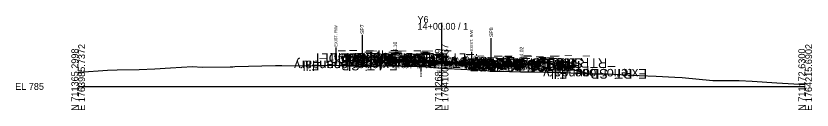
# Model space of a CAD drawing. Extents: x -26 to 1764234, y -10 to 711417.
# Drawn here: x -25.7 to 302.8, y 3990.3 to 4029 of the extents above; entities that cross this region are included whole.
import ezdxf

# ---------------------------------------------------------------- set-up
doc = ezdxf.new("R2010")
doc.units = 0
for name, color, linetype in [('Default', 7, 'Continuous'), ('Exist Cross Section Cell', 7, 'Continuous'), ('Exist XS Center Line Elevation Label', 7, 'Continuous'), ('Exist XS Ground Line', 7, 'Continuous'), ('Old_Level_10', 7, 'Continuous'), ('Prop CMT Conc Surface', 7, 'Continuous'), ('Prop CMT Concrete Structures', 7, 'Continuous'), ('Prop CMT Pvmt Course 1', 7, 'Continuous'), ('Prop CMT Pvmt Course 1 CG', 7, 'Continuous'), ('Prop CMT Pvmt Course 2', 7, 'Continuous'), ('Prop CMT Pvmt Course 3', 7, 'Continuous'), ('Prop CMT Pvmt Surface', 7, 'Continuous'), ('Prop CMT Slope Grass', 7, 'Continuous'), ('Prop CMT Subgrade Earthwork', 7, 'Continuous'), ('Prop XS Earthwork Shape', 7, 'Continuous'), ('Prop XS Hydro Elevations', 7, 'Continuous'), ('Prop XS SE Text', 7, 'Continuous'), ('Prop XS Shear Point Element', 7, 'Continuous'), ('Prop XS Shear Point Label', 7, 'Continuous'), ('Prop XS Side Slope Text', 7, 'Continuous'), ('Scratch_Level_7', 7, 'Continuous')]:
    doc.layers.add(name, color=color, linetype=linetype)

msp = doc.modelspace()

# ---------------------------------------------------------------- linework, layer by layer
at = {"layer": 'Exist Cross Section Cell'}
for p, q in [((150, 4000), (150, 4026.15)), ((0, 4000), (150, 4000)), ((150, 4000), (300, 4000))]:
    msp.add_line(p, q, dxfattribs=at)
at = {"layer": 'Exist XS Ground Line'}
msp.add_lwpolyline([(0, 4005.86), (0.45, 4005.87), (12.06, 4006.66), (16.03, 4006.86), (25.11, 4006.99), (31.6, 4007.29), (38.16, 4007.69), (47.17, 4008.15), (51.21, 4007.99), (62.74, 4008.02), (63.8, 4008.12), (64.63, 4008.19), (81.43, 4008.58), (84, 4008.56), (94.28, 4008.5), (95.25, 4008.52), (95.84, 4008.53), (98.52, 4008.59), (99.73, 4008.62), (101.78, 4008.65), (103.62, 4008.7), (105.04, 4008.72), (107.52, 4008.64), (108.3, 4008.61), (111.56, 4008.47), (112.35, 4008.45), (115.04, 4008.38), (117.48, 4008.34), (118.51, 4008.29), (119.6, 4008.35), (120.21, 4008.44), (120.97, 4008.37), (121.35, 4008.36), (123.09, 4008.39), (124.61, 4008.42), (126.98, 4008.48), (127.87, 4008.49), (129.19, 4008.51), (129.93, 4008.52), (130.64, 4008.51), (131.28, 4008.49), (132.79, 4008.46), (134.39, 4008.4), (134.76, 4008.39), (137.65, 4008.34), (138.66, 4008.32), (139.89, 4008.3), (140.8, 4008.27), (141.45, 4008.24), (143.36, 4008.06), (150, 4007.53), (151.69, 4007.4), (152.53, 4007.34), (168.68, 4006.5), (169.94, 4006.35), (170.66, 4006.32), (173.38, 4006.32), (182.5, 4006.05), (188.46, 4006.02), (193.38, 4005.87), (194.39, 4005.86), (201.11, 4005.81), (210.23, 4005.22), (218.47, 4005.21), (220.83, 4005.07), (226.85, 4004.79), (231.52, 4004.49), (238.57, 4004.21), (246.23, 4003.88), (249.17, 4003.68), (261.86, 4002.42), (272.69, 4002.41), (278.12, 4002.22), (288.3, 4001.56), (295.35, 4001.03), (300, 4000.74)], dxfattribs=at)
at = {"layer": 'Old_Level_10'}
for p, q in [((106.29, 4016.08), (106.29, 4008.68)), ((162.3, 4014.23), (162.3, 4006.83)), ((141.45, 4008.24), (141.45, 4006.19))]:
    msp.add_line(p, q, dxfattribs=at)
at = {"layer": 'Prop CMT Conc Surface'}
for points in [[(130.8, 4011.1), (130.8, 4011.6), (130.3, 4011.6)], [(132.8, 4011.1), (130.8, 4011.1)], [(180.97, 4009.18), (182.97, 4009.02)], [(182.97, 4009.02), (182.97, 4009.52), (183.47, 4009.52)]]:
    msp.add_lwpolyline(points, dxfattribs=at)
at = {"layer": 'Prop CMT Concrete Structures'}
for points in [[(132.8, 4011.1), (130.8, 4011.1), (130.8, 4011.6), (130.3, 4011.6)], [(130.3, 4011.6), (130.3, 4010.62), (132.8, 4010.52)], [(132.8, 4010.52), (132.8, 4011.1)], [(180.97, 4009.18), (182.97, 4009.02), (182.97, 4009.52), (183.47, 4009.52)], [(183.47, 4009.52), (183.47, 4008.49), (180.97, 4008.59)], [(180.97, 4008.59), (180.97, 4009.18)]]:
    msp.add_lwpolyline(points, dxfattribs=at)
at = {"layer": 'Prop CMT Pvmt Course 1'}
for points in [[(150, 4010.41), (132.8, 4011.1)], [(132.8, 4011.1), (132.8, 4010.85)], [(132.8, 4010.85), (150, 4010.16)], [(150, 4010.16), (150, 4010.41)], [(150, 4010.41), (180.97, 4009.18)], [(180.97, 4008.93), (150, 4010.16)], [(150, 4010.16), (150, 4010.16), (150, 4010.16), (150, 4010.16), (150, 4010.16)], [(180.97, 4009.18), (180.97, 4008.93)]]:
    msp.add_lwpolyline(points, dxfattribs=at)
msp.add_lwpolyline([(150, 4010.16), (150, 4010.16), (150, 4010.16), (150, 4010.16)], close=True, dxfattribs=at)
at = {"layer": 'Prop CMT Pvmt Course 1 CG'}
for points in [[(132.8, 4010.52), (129.8, 4010.64), (129.48, 4010.32)], [(129.48, 4010.32), (132.8, 4010.19)], [(132.8, 4010.19), (132.8, 4010.52)], [(180.97, 4008.59), (183.97, 4008.47), (184.32, 4008.12)], [(180.97, 4008.26), (180.97, 4008.59)], [(184.32, 4008.12), (180.97, 4008.26)]]:
    msp.add_lwpolyline(points, dxfattribs=at)
at = {"layer": 'Prop CMT Pvmt Course 2'}
for points in [[(150, 4010.16), (132.8, 4010.85)], [(132.8, 4010.85), (132.8, 4010.52)], [(132.8, 4010.52), (150, 4009.83)], [(150, 4009.83), (150, 4010.16)], [(150, 4009.83), (150, 4010.16)], [(150, 4010.16), (180.97, 4008.93)], [(180.97, 4008.59), (150, 4009.83)], [(180.97, 4008.93), (180.97, 4008.59)]]:
    msp.add_lwpolyline(points, dxfattribs=at)
at = {"layer": 'Prop CMT Pvmt Course 3'}
for points in [[(150, 4009.83), (132.8, 4010.52)], [(132.8, 4010.52), (132.8, 4010.19)], [(132.8, 4010.19), (150, 4009.5)], [(150, 4009.5), (150, 4009.83)], [(150, 4009.83), (180.97, 4008.59)], [(150, 4009.5), (150, 4009.83)], [(180.97, 4008.26), (150, 4009.5)], [(180.97, 4008.59), (180.97, 4008.26)]]:
    msp.add_lwpolyline(points, dxfattribs=at)
at = {"layer": 'Prop CMT Pvmt Surface'}
for points in [[(150, 4010.41), (132.8, 4011.1)], [(150, 4010.41), (180.97, 4009.18)]]:
    msp.add_lwpolyline(points, dxfattribs=at)
at = {"layer": 'Prop CMT Slope Grass'}
msp.add_line((117.37, 4011.3), (117.37, 4008.35), dxfattribs=at)
for points in [[(130.3, 4011.6), (120.8, 4011.79), (117.37, 4011.3)], [(183.47, 4009.52), (192.97, 4009.71), (210.92, 4005.22)]]:
    msp.add_lwpolyline(points, dxfattribs=at)
at = {"layer": 'Prop CMT Subgrade Earthwork'}
for points in [[(132.8, 4010.19), (129.48, 4010.32), (128.15, 4011.65)], [(150, 4009.5), (132.8, 4010.19)], [(150, 4009.5), (180.97, 4008.26)], [(180.97, 4008.26), (184.32, 4008.12), (185.75, 4009.56)]]:
    msp.add_lwpolyline(points, dxfattribs=at)
at = {"layer": 'Prop XS Earthwork Shape'}
msp.add_lwpolyline([(108.3, 4008.61), (111.56, 4008.47), (112.35, 4008.45), (115.04, 4008.38), (117.48, 4008.34), (118.51, 4008.29), (119.6, 4008.35), (120.21, 4008.44), (120.97, 4008.37), (121.35, 4008.36), (123.09, 4008.39), (124.61, 4008.42), (126.98, 4008.48), (127.87, 4008.49), (129.19, 4008.51), (129.93, 4008.52), (130.64, 4008.51), (131.28, 4008.49), (132.79, 4008.46), (134.39, 4008.4), (134.76, 4008.39), (137.65, 4008.34), (138.66, 4008.32), (139.89, 4008.3), (140.8, 4008.27), (141.45, 4008.24), (143.36, 4008.06), (150, 4007.53), (151.69, 4007.4), (152.53, 4007.34), (168.68, 4006.5), (169.94, 4006.35), (170.66, 4006.32), (173.38, 4006.32), (182.5, 4006.05), (188.46, 4006.02), (193.38, 4005.87), (194.39, 4005.86), (201.11, 4005.81), (210.23, 4005.22), (210.92, 4005.22), (192.97, 4009.71), (185.75, 4009.56), (184.32, 4008.12), (180.97, 4008.26), (150, 4009.5), (132.8, 4010.19), (129.48, 4010.32), (128.15, 4011.65), (120.8, 4011.79), (108.11, 4008.62)], close=True, dxfattribs=at)
at = {"layer": 'Prop XS Shear Point Element'}
for p, q in [((117.37, 4011.3), (117.37, 4021.23)), ((170.43, 4009.6), (170.43, 4019.88))]:
    msp.add_line(p, q, dxfattribs=at)

# ---------------------------------------------------------------- texts
at = {"layer": 'Default'}
msp.add_text('-', height=0.0001, dxfattribs=at).set_placement((0, 4000))
at = {"layer": 'Exist Cross Section Cell'}
for s, p in [('Y6', (140, 4026.15)), ('14+00.00 / 1', (140, 4023.35)), ('EL 785', (-26, 3998.6))]:
    msp.add_text(s, height=2.8, dxfattribs=at).set_placement(p)
for s, p in [('N 711365.2998', (0, 3990)), ('E 1763985.7372', (2.8, 3990)), ('N 711268.9649', (150, 3990)), ('E 1764100.7137', (152.8, 3990)), ('N 711172.6300', (300, 3990)), ('E 1764215.6902', (302.8, 3990))]:
    msp.add_text(s, height=2.8, rotation=90, dxfattribs=at).set_placement(p)
at = {"layer": 'Exist XS Center Line Elevation Label'}
msp.add_text('792.53', height=1, dxfattribs=at).set_placement((147.88, 4005.53))
at = {"layer": 'Old_Level_10'}
for s, height, p in [('EXIST. R/W', 1.181, (106.88, 4016.38)), ('EXIST. R/W', 1.181, (162.89, 4014.54)), ('EOP', 0.787, (141.85, 4003.79))]:
    msp.add_text(s, height=height, rotation=90, dxfattribs=at).set_placement(p)
at = {"layer": 'Prop XS Hydro Elevations'}
for s, p in [('796.10', (131.55, 4012.1)), ('794.02', (183.72, 4010.02))]:
    msp.add_text(s, height=1.5, rotation=90, dxfattribs=at).set_placement(p)
at = {"layer": 'Prop XS SE Text'}
for p in [(138.82, 4011.86), (162.9, 4010.9)]:
    msp.add_text('0.040', height=1.5, rotation=357.7094, dxfattribs=at).set_placement(p)
at = {"layer": 'Prop XS Shear Point Label'}
for s, p in [('SP7', (117.99, 4021.59)), ('SP8', (171.18, 4020.36))]:
    msp.add_text(s, height=1.5, rotation=90, dxfattribs=at).set_placement(p)
at = {"layer": 'Prop XS Side Slope Text'}
for s, rotation, p in [('VAR.', 14.0362, (117.71, 4011.61)), ('4:1', 345.9638, (200.98, 4008.48))]:
    msp.add_text(s, height=1.5, rotation=rotation, dxfattribs=at).set_placement(p)
at = {"layer": 'Scratch_Level_7'}
for s, p in [('LT_Sub_Trench_Out_DLT', (160.18, 4013.65)), ('LT_CSLP_Pnt', (138.18, 4013.79)), ('LT_CG_Top_BOC', (151.21, 4013.6)), ('LT_CG_Top_Face', (152.62, 4013.6)), ('Exterior Boundary', (131.89, 4010.62)), ('LT_Slope_Fill', (125.39, 4010.62)), ('LT_CG1_Shelf_Out', (152.54, 4012.64)), ('LT_CG_Bot_BOC', (150.77, 4012.62)), ('LT_CG_Top_Gut', (150.67, 4013.1)), ('LT_Sub_OEOP', (147.67, 4012.32)), ('LT_PV1_OEOT', (150.43, 4013.1)), ('LT_PV2_OEOT', (151.44, 4012.85)), ('LT_PV3_OEOT', (151.47, 4012.52)), ('LT_Sub_OEOT', (150.91, 4012.19)), ('LT_CG_Bot_IE', (150.78, 4012.52)), ('RT_PV1_OEEOP', (170.2, 4012.16)), ('LT_PV1_OEEOP', (169.7, 4012.16)), ('RT_PV2_OEEOP', (171.21, 4012.16)), ('RT_PV3_OEEOP', (171.24, 4011.83)), ('RT_Sub_OEEOP', (170.67, 4011.5)), ('LT_PV2_OEEOP', (170.71, 4012.16)), ('LT_PV3_OEEOP', (170.74, 4011.83)), ('LT_Sub_OEEOP', (170.17, 4011.5)), ('RT_PV1_IEEOP', (169.32, 4012.16)), ('LT_PV1_IEEOP', (168.82, 4012.16)), ('RT_PV2_IEEOP', (170.33, 4012.16)), ('LT_PV2_IEEOP', (169.82, 4012.16)), ('PV1_PGL', (160.68, 4012.41)), ('PV2_PGL', (161.68, 4012.16)), ('RT_Sub_Trench_Out_DLT', (218.28, 4011.56)), ('RT_CG1_Shelf_Out', (207.21, 4010.47)), ('RT_CG_Top_BOC', (204.89, 4011.52)), ('RT_CG_Top_Face', (205.3, 4011.52)), ('RT_PV1_OEOT', (199.11, 4011.18)), ('RT_CG_Bot_BOC', (204.44, 4010.49)), ('RT_CG_Top_Gut', (203.35, 4011.02)), ('RT_PV2_OEOT', (200.12, 4010.93)), ('RT_PV3_OEOT', (200.15, 4010.59)), ('RT_Sub_OEOT', (199.58, 4010.26)), ('RT_CG_Bot_IE', (199.46, 4010.59)), ('RT_CSLP_Pnt', (210.86, 4011.71)), ('RT_Sub_OEOP', (203.01, 4010.12)), ('Exterior Boundary', (234.7, 4007.22)), ('RT_Slope_Fill', (228.7, 4007.22))]:
    msp.add_text(s, height=4, rotation=180, dxfattribs=at).set_placement(p)

doc.saveas('drawing.dxf')
